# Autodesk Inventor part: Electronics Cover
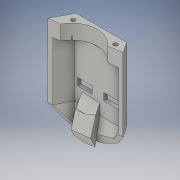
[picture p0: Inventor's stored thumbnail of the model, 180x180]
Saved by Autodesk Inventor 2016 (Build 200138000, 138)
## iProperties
Created: 2015-09
Part Number: Electronics Cover
Material: Generic
Document SubType Name: Modeling
Designer: Z
Density: 1 g/cm^3
Appearance: Default
Author: Z
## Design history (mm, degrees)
derived "cane mount.ipt"
  sketch "Sketch37"
    geometry: L1 (7.76, 0)-(8.043, 0) reference; L2 (19.064, 57.15)-(19.064, 0) reference; L3 (15.314, 0)-(15.314, 50.8) reference; L4 (15.314, 50.8)-(8.043, 50.8) reference; L5 (8.043, 0)-(8.043, 50.8) reference; L6 (8.043, 57.15)-(19.064, 57.15) reference; L7 (8.043, 50.8)-(8.043, 57.15) reference; L8 (0, 50.8)-(0, 0) reference; L9 (7.76, 50.8)-(7.76, 0) reference; L10 (7.76, 50.8)-(0, 50.8) reference; L11 (-3.767, 0)-(-3.767, 63.5) reference; L12 (-3.767, 63.5)-(7.76, 63.5) reference; L13 (7.76, 63.5)-(7.76, 50.8) reference; L14 (15.314, 3.175)-(0, 3.175) reference; L15 (0, 3.175)-(0, 15.875) reference; L16 (0, 15.875)-(15.314, 15.875) reference; L17 (15.314, 15.875)-(15.314, 3.175) reference; 5 further points
  sketch "Sketch38"
    geometry: L1 (-12.361, 64.822)-(-4.847, 64.822) reference; L2 (-4.847, 64.822)-(7.871, 9.897) reference; L3 (7.871, 9.897)-(5.044, 0.782) reference; L4 (-56.252, 0.782)-(-58.671, 11.761) reference; L5 (-58.671, 11.761)-(-43.805, 64.822) reference; L6 (-43.805, 64.822)-(-37.173, 64.822) reference; L7 (-40.964, 57.706)-(-42.061, 57.706) reference; L8 (-42.061, 57.706)-(-55.048, 11.353) reference; L9 (-55.048, 11.353)-(-52.719, 0.782) reference; L10 (1.192, 0.782)-(4.181, 10.421) reference; L11 (4.181, 10.421)-(-6.768, 57.706) reference; L12 (-6.768, 57.706)-(-8.569, 57.706) reference; L13 (-24.767, 23.835)-(-24.767, -28.939) reference; C1 r 1.5 at (-24.767, -22.589) reference; 14 further points; 3 other entities
    constraints: 3 other
  sketch "Sketch39"
    geometry: L1 (-25.388, 57.15)-(-14.362, 57.15) reference; L2 (-14.362, 57.15)-(-14.362, 50.8) reference; L3 (-14.362, 50.8)-(-14.362, 0) reference; L4 (-14.362, 0)-(-14.4, 0) reference; L5 (-21.781, 50.8)-(-21.781, 0) reference; L6 (-14.362, 50.8)-(-21.781, 50.8) reference; L7 (-25.388, 0.007)-(-25.388, 57.15) reference; L8 (-14.4, 0)-(-7.597, -10.524) reference; L9 (-7.597, -10.524)-(-14.054, 0) reference; L10 (0, 50.8)-(-14.054, 50.8) reference; L11 (-14.054, 0)-(-14.054, 50.8) reference; L12 (-14.054, 50.8)-(-14.054, 63.5) reference; L13 (-14.054, 63.5)-(3.595, 63.5) reference; L14 (3.595, 63.5)-(3.595, 0.004) reference; L15 (0, 0)-(0, 50.8) reference; L16 (-21.781, 25.4)-(0, 25.4) reference; L17 (0, 25.4)-(0, 6.35) reference; L18 (0, 6.35)-(-21.781, 6.35) reference; L19 (-21.781, 6.35)-(-21.781, 25.4) reference; 3 further points
sketch "Sketch4"
  geometry: L1 (1.109, 50.8)-(1.109, 63.5) reference; L2 (1.109, 63.5)-(22.333, 63.5) reference; L3 (22.333, 63.5)-(22.333, 0) reference; L4 (10.368, -15.64)-(-12.495, -20.794) reference; L5 (-25.465, 0.001)-(-25.465, 63.5) reference; L6 (-25.465, 63.5)-(-6.375, 63.5) reference; L7 (-6.375, 63.5)-(-6.375, 50.8) reference; L8 (-6.375, 50.8)-(1.109, 50.8) reference; L9 (18.566, 50.8)-(1.109, 50.8) reference; L10 (18.566, 0)-(18.566, 50.8) reference; L11 (0, 9.242)-(0, 0) reference; L12 (-15.471, 10.134)-(0, 9.242) reference; L13 (-15.471, 0)-(-15.471, 10.134) reference; L14 (-21.871, 50.8)-(-21.871, 0) reference; L15 (-6.375, 50.8)-(-21.871, 50.8) reference; L16 (-6.732, 19.05)-(-19.432, 19.05); L17 (-19.432, 19.05)-(-19.432, 12.7); L18 (-19.432, 12.7)-(-6.732, 12.7); L19 (-6.732, 12.7)-(-6.732, 19.05); L20 (16.128, 19.05)-(3.428, 19.05); L21 (3.428, 19.05)-(3.428, 12.7); L22 (3.428, 12.7)-(16.128, 12.7); L23 (16.128, 12.7)-(16.128, 19.05); L24 (-21.871, 25.4)-(18.566, 25.4); L25 (-1.652, 25.4)-(-1.652, 0); L26 (-21.871, 0)-(18.566, 0); L27 (-6.732, 12.7)-(-1.652, 12.7); L28 (3.428, 12.7)-(-1.652, 12.7); 4 further points
  constraints: 26 end point, 5 equal length, 5 midpoint, 3 horizontal, 2 collinear, 2 horizontal alignment, 2 perpendicular, 2 point on line, 1 vertical, 5 other
  dimensions: "d1" = 12.7 distance of L17.end L18.end; "d2" = 10.16 distance between parallel lines of L21 L19; "d3" = 6.35 distance of L16.end L17.end
extrude "Extrusion1" cut sketch "Sketch4" stored distance "d4" = 25.4; taper "d5" = 0 deg
feature "Solid17::cane mount.ipt" dims "d0" = 10
tag "TaggingFeature1"
workplane "Work Plane6"
workplane "Work Plane7"
workplane "Work Plane14"
workaxis "Work Axis2"
body "Solid1"
node "Project Cut Edges1"
